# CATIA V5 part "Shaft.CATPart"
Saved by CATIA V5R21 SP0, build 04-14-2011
Part number: 01
Material "Dull Orange": density 7860 kg/m3, Young's modulus 2e+11 Pa, Poisson ratio 0.266
Bounding box of the stored display mesh (mm): x 0 to 11, y -12 to 12, z -30 to 15
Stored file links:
  G:\CATIA\Universial Joint\Shaft.CATPart
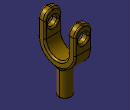
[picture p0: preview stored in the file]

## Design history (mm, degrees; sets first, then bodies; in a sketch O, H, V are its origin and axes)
Body1 (main body), material "Dull Orange"
  Sketch1 on yz-plane, origin (0, 0, 0), H (0, 1, 0), V (0, 0, 1)
    arc A1 centre (0, 0) radius 7.5 from (-7.5, 0) to (7.5, 0) ccw
    arc A2 centre (0, 0) radius 12 from (-12, 0) to (12, 0) ccw
    point P1 (-12, 0)
    point P2 (12, 0)
    point P3 (-7.5, 0)
    point P4 (7.5, 0)
    line L1 (7.5, 0) -> (7.5, 15)
    point P5 (7.5, 0)
    point P6 (7.5, 15)
    line L2 (12, 0) -> (12, 15)
    point P7 (12, 15)
    line L3 (12, 15) -> (7.5, 15)
    point P8 (-12, 0)
    point P9 (-7.5, 0)
    point P10 (-7.5, 0)
    point P11 (-7.5, 15)
    point P12 (-12, 15)
    line L4 (-7.5, 0) -> (-7.5, 15)
    line L5 (-12, 0) -> (-12, 15)
    line L6 (-12, 15) -> (-7.5, 15)
    radius A2 = 12
    radius A1 = 7.5
    length L2 = 15
    length L3 = 4.5
    coincidence: P1 H, P5 A1, P1 P8, P3 P10, P4 P5
    vertical: L1 V, L2 V
    tangency: L2 A2
    horizontal: L3 H
    symmetry: P2 P8 V, P4 P9 V, P5 P10 V, P6 P11 V, P7 P12 V, L1 L4 V, L2 L5 V, L3 L6 V
  Pad1: profile Sketch1, direction (1, 0, 0), length 11
  Sketch2 on zx-plane, origin (0, 0, 0), H (-1, 0, 0), V (0, 0, 1)
    circle A1 centre (-5.5, 7.5) radius 3
    point P1 (-5.5, 7.5)
    reference projected line E1 (0, 15) -> (-11, 15) from edge [face of Pad1 from Sketch1.L3 | face of Pad1 from Sketch1.L2]
    reference projected line E2 (-11, 0) -> (-11, 15) from edge [face of Pad1 from Sketch1.L2 | end face of Pad1]
    radius A1 = 3
    distance E1 P1 = 7.5
    distance P1 E2 = 5.5
  Pocket1: profile Sketch2, direction (0, -1, 0), length 30, mirrored extent
  Plane1: type Offset, RefPlane xy-plane, Offset 10, reversed
  Sketch3 on Plane1, origin (0, 0, -10), H (1, 0, 0), V (0, 1, 0)
    circle A1 centre (5.5, 0) radius 3.75
    point P1 (5.5, 0)
    reference projected line E1 (0, 12) -> (0, 7.5) from edge [start face of Pad1 | face of Pad1 from Sketch1.L3]
    radius A1 = 3.75
    distance E1 P1 = 5.5
    coincidence: P1 H
  Pad2: profile Sketch3, direction (0, 0, -1), length 20
  Fillet1: radius 5, on edge [face of Pad1 from Sketch1.L6 | end face of Pad1]; edge [start face of Pad1 | face of Pad1 from Sketch1.L6]; edge [start face of Pad1 | face of Pad1 from Sketch1.L3]; edge [face of Pad1 from Sketch1.L3 | end face of Pad1]
  Fillet2: radius 2, on edge [face of Pad2 from Sketch3.A1 | face of Pad1 from Sketch1.A2]
  Fillet3: radius 1, on face of Pad1 from Sketch1.L2; face of Pad1 from Sketch1.A1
